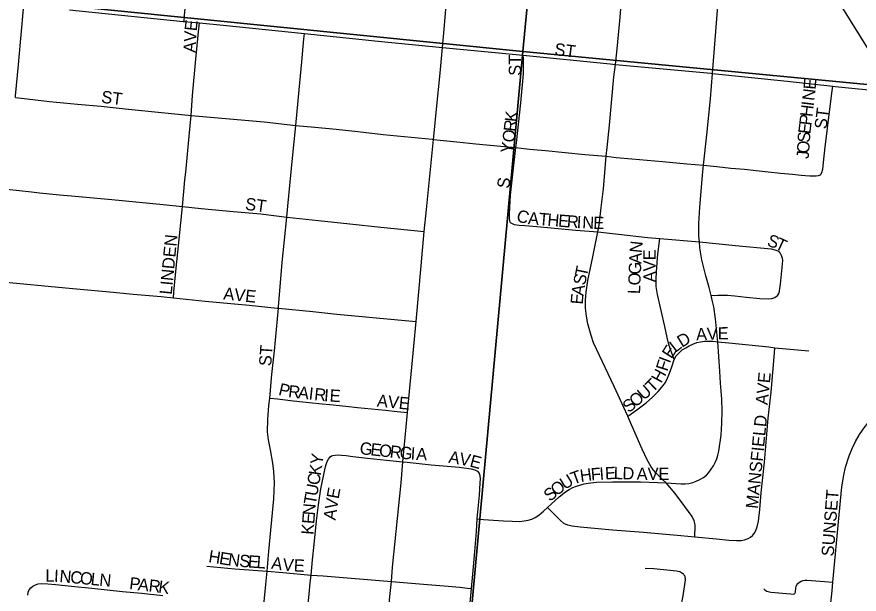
# Model space of a CAD drawing. Extents: x 1410790 to 1770854, y 566777 to 831614.
# Drawn here: x 1601630 to 1605056, y 695774 to 698124 of the extents above; entities that cross this region are included whole.
import ezdxf

# ---------------------------------------------------------------- set-up
doc = ezdxf.new("R2010")
doc.units = 0
for name, color, linetype in [('GM_X_City_Street', 7, 'Continuous'), ('GM_X_City_Street_Text', 7, 'Continuous'), ('GM_X_Section', 7, 'Continuous')]:
    doc.layers.add(name, color=color, linetype=linetype)

msp = doc.modelspace()

# ---------------------------------------------------------------- linework, layer by layer
at = {"layer": 'GM_X_City_Street'}
for points in [[(1602309.9, 698105), (1602312.2, 698129.9), (1602321.5, 698227.3), (1602333.2, 698374.1), (1602342.6, 698477.6)], [(1603360.8, 697999.6), (1603367.6, 698073.2), (1603378.5, 698203.8), (1603388.3, 698316.2), (1603393.6, 698384.7)], [(1604064.4, 697930.5), (1604071.3, 697993.4), (1604082.4, 698107.7), (1604099.4, 698302.8), (1604100.6, 698318.5)], [(1604459.5, 697893.6), (1604481.7, 698166.9), (1604493.3, 698273.6), (1604493.9, 698279.8)], [(1605178.8, 697845.3), (1605169, 697862.3), (1605103.4, 697975.9), (1604982.7, 698169.4), (1604942.5, 698234.5), (1604931.2, 698252.7)], [(1601623.8, 697796.1), (1601624.4, 697802.6), (1601636, 697929.1), (1601638.8, 697959.2), (1601646, 698036.2), (1601658.5, 698171)], [(1601843.6, 698152.1), (1602306.4, 698105.3), (1602309.9, 698105)], [(1602309.9, 698105), (1602372.4, 698099.2)], [(1602339.2, 697722.7), (1602344.4, 697803.4), (1602358.2, 697951.3), (1602368.9, 698063.3), (1602372.4, 698099.2)], [(1602372.4, 698099.2), (1602468.5, 698090.4), (1602799.6, 698056.2)], [(1602764.5, 697681.9), (1602777.5, 697826.8), (1602789, 697940.9), (1602797.6, 698034.8), (1602799.6, 698056.2)], [(1602799.6, 698056.2), (1603099.6, 698025.3), (1603360.8, 697999.6)], [(1603324.8, 697625.2), (1603327.2, 697649.8), (1603337.2, 697747.5), (1603351.1, 697894), (1603360.8, 697999.6)], [(1603360.8, 697999.6), (1603690, 697967.2)], [(1603659.1, 697591.4), (1603661.8, 697610.4), (1603679.5, 697773.9), (1603690.3, 697892.1), (1603690.9, 697923.5), (1603690.3, 697954.1), (1603690, 697967.2)], [(1603690, 697967.2), (1604043.7, 697932.4), (1604064.4, 697930.5)], [(1604026.7, 697556.6), (1604030.7, 697592.2), (1604040.7, 697683.6), (1604058.6, 697879.4), (1604064.4, 697930.5)], [(1604064.4, 697930.5), (1604452.6, 697894.1), (1604459.5, 697893.6)], [(1604422.9, 697519.8), (1604435.9, 697643), (1604451.1, 697790), (1604459.5, 697893.6)], [(1604459.5, 697893.6), (1604763.1, 697862.2), (1604949.2, 697841.1)], [(1604899.4, 697481.4), (1604903.8, 697490.1), (1604908, 697504.2), (1604909.8, 697515.6), (1604911.7, 697530.9), (1604918.5, 697594.7), (1604922.5, 697626.4), (1604930.3, 697693.3), (1604946.9, 697823.2), (1604949.2, 697841.1)], [(1604949.2, 697841.1), (1604958.9, 697840), (1605053.6, 697830.3), (1605096.5, 697827), (1605119.6, 697829.2), (1605136.4, 697831.2), (1605151.9, 697833.9), (1605166.5, 697839), (1605178.8, 697845.3)], [(1601623.8, 697796.1), (1601648.6, 697793.2), (1601762.1, 697779.7), (1601875.8, 697769), (1601973.2, 697760), (1602070.7, 697749.9), (1602232.1, 697732.5), (1602327.1, 697723.8), (1602339.2, 697722.7)], [(1602302.9, 697352.4), (1602308.7, 697413.1), (1602313.5, 697460.3), (1602316.9, 697492.3), (1602331.2, 697638.5), (1602339.2, 697722.7)], [(1602339.2, 697722.7), (1602635.2, 697695.9), (1602764.5, 697681.9)], [(1602727.3, 697308.9), (1602732.5, 697353), (1602750.9, 697549.3), (1602764.5, 697681.9)], [(1602764.5, 697681.9), (1602841.8, 697674.4), (1602928.6, 697666.6), (1603017.2, 697656.9), (1603120, 697645.2), (1603205, 697636.5), (1603319.2, 697625.9), (1603324.8, 697625.2)], [(1603287.2, 697250.7), (1603296.3, 697339.4), (1603324.8, 697625.2)], [(1603324.8, 697625.2), (1603420, 697615.2), (1603496.3, 697607), (1603597.8, 697597.1), (1603659.1, 697591.4)], [(1603636.6, 697287.3), (1603633.3, 697302.9), (1603633.3, 697321.1), (1603634.9, 697348.2), (1603637.5, 697397.9), (1603648.3, 697496.1), (1603659.1, 697591.4)], [(1603659.1, 697591.4), (1603715.5, 697585.8), (1603780, 697579.3), (1603940.4, 697564), (1604026.7, 697556.6)], [(1603992.8, 697248.4), (1603998.2, 697275.9), (1604007.3, 697348.1), (1604016.2, 697424.3), (1604026.7, 697556.6)], [(1604026.7, 697556.6), (1604067, 697551.9), (1604131.5, 697546.3), (1604255.5, 697534.6), (1604355.7, 697525), (1604422.9, 697519.8)], [(1604406.4, 697207.5), (1604404.3, 697232.8), (1604404.1, 697282.4), (1604407.6, 697348.3), (1604419.1, 697479.4), (1604422.9, 697519.8)], [(1604422.9, 697519.8), (1604477.8, 697514.5), (1604534.5, 697508.4), (1604590.3, 697503.2), (1604637.3, 697498.9), (1604686.2, 697492.8), (1604735.9, 697487.5), (1604785.6, 697483.2), (1604819.6, 697479.7), (1604855.3, 697476.3), (1604880.7, 697476.3), (1604890.9, 697477.9), (1604899.4, 697481.4)], [(1601589.2, 697422.4), (1601689.2, 697411.1), (1601721.8, 697407.6), (1601803.3, 697400), (1601852.2, 697396), (1602016.3, 697380.4), (1602224.8, 697360.5), (1602302.9, 697352.4)], [(1602266.3, 696980.4), (1602268.5, 697002.9), (1602275.6, 697073.5), (1602290.2, 697219.3), (1602302.9, 697352.4)], [(1602302.9, 697352.4), (1602379.5, 697344.3), (1602509.9, 697331.8), (1602621.9, 697321.5), (1602727.3, 697308.9)], [(1602694.1, 696938), (1602694.6, 696944), (1602709, 697124.2), (1602727.3, 697308.9)], [(1602727.3, 697308.9), (1602857, 697295), (1602984.4, 697281.7), (1603110.4, 697268.4), (1603287.2, 697250.7)], [(1603636.6, 697287.3), (1603653.1, 697279), (1603672.9, 697275.7), (1603696.1, 697274), (1603744.9, 697269.9), (1603903.3, 697255.4), (1603992.8, 697248.4)], [(1603253.4, 696883.9), (1603274.2, 697110.6), (1603287.2, 697250.7)], [(1604114.9, 696498.4), (1604059, 696619), (1603975.4, 696796.8), (1603965.4, 696826.8), (1603952.1, 696874.2), (1603946.8, 696906), (1603942.7, 696938.2), (1603942.5, 696970.5), (1603945.2, 697002.8), (1603952.3, 697051), (1603972.3, 697147.1), (1603992.8, 697248.4)], [(1603992.8, 697248.4), (1604077, 697239.3), (1604195.5, 697225.8), (1604245.1, 697221.5)], [(1604303.5, 696729.2), (1604298.4, 696743.8), (1604288.6, 696770.1), (1604282.2, 696789.8), (1604275.3, 696819.2), (1604266, 696863.7), (1604235.7, 696993.6), (1604232.7, 697010), (1604231, 697025.9), (1604230, 697043), (1604230.5, 697059.5), (1604231.9, 697085.1), (1604234.4, 697123.5), (1604237, 697157.7), (1604245.1, 697221.5)], [(1604245.1, 697221.5), (1604406.4, 697207.5)], [(1604406.4, 697207.5), (1604552.8, 697192.7), (1604698.3, 697179.1), (1604713.4, 697175.7), (1604720.9, 697173.3), (1604727.5, 697170.2), (1604732.4, 697165.3), (1604736.2, 697160)], [(1604453.8, 696989.1), (1604445.8, 697021.9), (1604432.7, 697070.2), (1604416.5, 697134.2), (1604408.4, 697183.3), (1604406.4, 697207.5)], [(1604724.3, 696990), (1604725.5, 696991), (1604729.1, 696998.1), (1604731.8, 697007.5), (1604734.1, 697018.4), (1604736.4, 697036.3), (1604744.7, 697117.5), (1604745.2, 697133.6), (1604744.5, 697140.8), (1604740.5, 697151.9), (1604736.2, 697160)], [(1601554.3, 697046.8), (1601842.5, 697019.3), (1602021.9, 697002.7), (1602103, 696994.8), (1602216.4, 696985.4), (1602266.3, 696980.4)], [(1602266.3, 696980.4), (1602395.4, 696967.2), (1602574.2, 696949.7), (1602688, 696938.6), (1602694.1, 696938)], [(1604453.8, 696989.1), (1604481.1, 696990.4), (1604500.4, 696991.4), (1604520.6, 696990.4), (1604550.1, 696987.7), (1604597, 696983.1), (1604652.2, 696977.6), (1604686.1, 696976.3), (1604701.4, 696977.6), (1604713.7, 696981.4), (1604724.3, 696990)], [(1604480.7, 696801.4), (1604479.8, 696813.2), (1604471.8, 696894.7), (1604464.5, 696943.2), (1604459.7, 696965.3), (1604453.8, 696989.1)], [(1602658.3, 696572.2), (1602667.2, 696668.3), (1602677.7, 696764.3), (1602694.1, 696938)], [(1602694.1, 696938), (1602834.3, 696924.3), (1602931.9, 696914), (1603209.1, 696888.1), (1603253.4, 696883.9)], [(1603218.5, 696513.9), (1603244.2, 696783.5), (1603253.4, 696883.9)], [(1604270.7, 696227.8), (1604332.1, 696223.4), (1604348.6, 696223.4), (1604363.5, 696224.9), (1604379.9, 696228.6), (1604392.6, 696233.8), (1604407.6, 696240.5), (1604422.5, 696248.8), (1604434.8, 696258.3), (1604445.3, 696269.7), (1604454.7, 696282.5), (1604463.1, 696296.3), (1604470.4, 696310.6), (1604476.8, 696325.4), (1604481.7, 696340.4), (1604484.9, 696356), (1604494.4, 696420.9), (1604498, 696469.6), (1604499, 696518.7), (1604497.2, 696567.7), (1604492.7, 696633), (1604489.9, 696682.2), (1604480.7, 696801.4)], [(1604303.5, 696729.2), (1604312.1, 696743.8), (1604324.9, 696758.3), (1604336.7, 696768), (1604351.2, 696776.4), (1604365.3, 696784.9), (1604380, 696792.1), (1604395.3, 696797.8), (1604411.3, 696801.6), (1604427.5, 696803.5), (1604460.3, 696803.4), (1604480.7, 696801.4)], [(1604480.7, 696801.4), (1604525.6, 696797.1), (1604689.4, 696780.3), (1604713.6, 696777.1)], [(1604623.6, 696014.8), (1604629, 696021.4), (1604636, 696033), (1604641.8, 696048.1), (1604646.1, 696071.2), (1604651.7, 696119.3), (1604657.3, 696186.8), (1604671.4, 696311.2), (1604686.1, 696490.7), (1604698.2, 696596.9), (1604711.7, 696756.6), (1604713.6, 696777.1)], [(1604713.6, 696777.1), (1604851.8, 696764.6)], [(1604114.9, 696498.4), (1604151.8, 696524.9), (1604189.8, 696553.4), (1604215.5, 696575.5), (1604238.5, 696599.6), (1604254, 696616.6), (1604267.7, 696636.2), (1604277.1, 696653.3), (1604284.8, 696673), (1604294.2, 696699.4), (1604303.5, 696729.2)], [(1605056.2, 696421.1), (1605057.8, 696423.8), (1605076, 696450.6), (1605106.2, 696488.8), (1605139.3, 696524.4), (1605163.1, 696546.3), (1605188.3, 696566.5), (1605215, 696584.7), (1605242.9, 696601), (1605272, 696615.2), (1605301.9, 696627.7), (1605332.5, 696638.4), (1605363.7, 696647.2), (1605395.3, 696654.1), (1605427.3, 696659), (1605459.6, 696661.9), (1605491.9, 696662.6), (1605524.2, 696661.1), (1605556.3, 696657.3), (1605588.2, 696651.4), (1605619.6, 696643.5), (1605665.9, 696628.6), (1605726.9, 696605.4), (1605728.5, 696604.7)], [(1602647.3, 695867.3), (1602654.8, 695949.2), (1602674.9, 696161.7), (1602678, 696226.7), (1602675.6, 696272.8), (1602670.7, 696307.2), (1602661.6, 696361.9), (1602653.2, 696401.8), (1602649.7, 696435.5), (1602651.1, 696484.6), (1602654.6, 696541.4), (1602658.3, 696572.2)], [(1602658.3, 696572.2), (1602689.6, 696568.7), (1602711.3, 696566.3), (1602743.4, 696562.8), (1602780.8, 696558.9), (1602818.9, 696554.8), (1602871.6, 696549.1), (1602902.4, 696545.9), (1602967.8, 696538.8), (1603016, 696533.9), (1603128.9, 696523.1), (1603177.2, 696518.1), (1603218.5, 696513.9)], [(1603200.3, 696313.3), (1603211.5, 696440.3), (1603218.5, 696513.9)], [(1604270.7, 696227.8), (1604257.5, 696239.8), (1604229.4, 696267.5), (1604219, 696279.4), (1604209.9, 696292.4), (1604194.3, 696320.5), (1604173.6, 696364.9), (1604121.1, 696485), (1604114.9, 696498.4)], [(1604949, 695822.9), (1604974.2, 696097.2), (1604985.6, 696210.8), (1604993.5, 696258.9), (1605000.9, 696290.4), (1605015.4, 696336.8), (1605027.4, 696366.8), (1605041.5, 696395.9), (1605056.2, 696421.1)], [(1602826.3, 695852.1), (1602831.9, 695914.1), (1602838.8, 695976), (1602848.8, 696072), (1602856.1, 696137.2), (1602866, 696202.2), (1602882.4, 696280), (1602886.3, 696298.3), (1602891.3, 696313.6), (1602897, 696323.8), (1602901.5, 696329.3), (1602904.7, 696332.6)], [(1602904.7, 696332.6), (1602909.9, 696336.5), (1602914.9, 696338.5), (1602924.5, 696340), (1602939.3, 696341.3), (1602950.7, 696340), (1602969.6, 696338.7), (1602996.2, 696334.9), (1603056.5, 696328.1), (1603133.9, 696319.8), (1603200.3, 696313.3)], [(1603153.3, 695825.6), (1603157.9, 695884.6), (1603192.7, 696227.6), (1603200.3, 696313.3)], [(1603200.3, 696313.3), (1603218, 696311.2), (1603315.4, 696300.1), (1603429.3, 696290.8), (1603477.7, 696284.4), (1603493.3, 696280.2), (1603506.3, 696273.4)], [(1603502.4, 696080.1), (1603503.4, 696095.5), (1603511.4, 696177.5), (1603513.1, 696201), (1603514.9, 696226.8), (1603515.5, 696243), (1603514.4, 696256.4), (1603511.9, 696264.7), (1603506.3, 696273.4)], [(1603788, 696127), (1603802.7, 696140.5), (1603836.3, 696170.7), (1603862.1, 696190.9), (1603876, 696200.1), (1603890.9, 696208), (1603906.4, 696214.2), (1603938.1, 696223.4), (1603954.4, 696226.5), (1603987.2, 696229.4), (1604052.4, 696231.9), (1604166.1, 696230.7), (1604270.7, 696227.8)], [(1604387.4, 696007.5), (1604388.1, 696019.5), (1604389.5, 696040.3), (1604389.6, 696056.8), (1604385.1, 696073.2), (1604376.4, 696090.2), (1604347.2, 696130.5), (1604308, 696183.8), (1604270.7, 696227.8)], [(1603502.4, 696080.1), (1603527.3, 696078.4), (1603609.6, 696073), (1603644.8, 696070.8), (1603673, 696070.4), (1603693.9, 696072.2), (1603709, 696074.8), (1603724.7, 696078.9), (1603738.1, 696085.8), (1603753.3, 696096), (1603772.2, 696112.3), (1603788, 696127)], [(1603788, 696127), (1603799.2, 696115.8), (1603829.2, 696086.1), (1603840.8, 696073.9), (1603853.3, 696063.4), (1603869.6, 696056.8), (1603888.2, 696052.1), (1603921.5, 696048.1), (1604052.5, 696036.3), (1604178.3, 696026.2), (1604330.6, 696012.7), (1604387.4, 696007.5)], [(1603479.2, 695797.4), (1603484.6, 695855), (1603490.8, 695931.3), (1603499.2, 696029.7), (1603502.4, 696080.1)], [(1604387.4, 696007.5), (1604476.3, 695999.3), (1604526.1, 695993.6), (1604557.3, 695992.1), (1604575.6, 695993.2), (1604589.8, 695995.9), (1604604.3, 696000.8), (1604614.5, 696006.3), (1604622.6, 696013.6), (1604623.6, 696014.8)], [(1602401.8, 695888.6), (1602516, 695877.9), (1602647.3, 695867.3)], [(1604329.9, 695715.7), (1604330.5, 695718.8), (1604340.2, 695767.2), (1604349.1, 695832.6), (1604349.3, 695837.1), (1604348.8, 695841.2), (1604347.8, 695845.4), (1604346.5, 695848.7), (1604343.6, 695853.1), (1604341, 695856.1), (1604335.3, 695860.1), (1604331.4, 695862.3), (1604326.5, 695864.4), (1604313.3, 695867.1), (1604221.3, 695876.6), (1604185, 695879)], [(1602600.2, 695383.3), (1602605.1, 695430.5), (1602607.6, 695457.4), (1602612.5, 695498.7), (1602620, 695574.7), (1602639.8, 695785.9), (1602647.3, 695867.3)], [(1602647.3, 695867.3), (1602712.2, 695862.1), (1602826.3, 695852.1)], [(1602780.2, 695361.6), (1602782, 695380.1), (1602785.8, 695420.3), (1602789.4, 695469.2), (1602802.8, 695617.7), (1602818.6, 695774.4), (1602823.1, 695820.4), (1602826.3, 695852.1)], [(1602826.3, 695852.1), (1602875.6, 695848.1), (1603153.3, 695825.6)], [(1601673.9, 695770.5), (1601676.2, 695782), (1601679.8, 695792.2), (1601686.3, 695800.1), (1601695, 695806.6), (1601705.1, 695812.5), (1601716, 695816.1), (1601731.2, 695817.5), (1601755.1, 695816.8), (1601786.2, 695813.9), (1601852.1, 695806.6), (1601934.7, 695798.7), (1602060, 695784.6), (1602136.7, 695777.7), (1602222.8, 695768.9)], [(1603105.7, 695332), (1603107.5, 695351.3), (1603116.9, 695450.6), (1603127.6, 695558.3), (1603146.8, 695764.1), (1603153.3, 695825.6)], [(1603153.3, 695825.6), (1603284.5, 695814.6), (1603383.7, 695806.4), (1603431.8, 695802.2), (1603462.4, 695798.6), (1603479.2, 695797.4)], [(1604668, 695796), (1604674.2, 695790.2), (1604680.6, 695786), (1604696.4, 695782.2), (1604776.9, 695775), (1604789.3, 695774.5), (1604792.6, 695775.7), (1604794.7, 695777.3), (1604796.3, 695779.5), (1604797.2, 695781.8), (1604799.2, 695799.3), (1604800.4, 695805.9), (1604803.2, 695811.5), (1604807.3, 695817.4), (1604813.5, 695823.3), (1604820.6, 695827.3), (1604828.3, 695829.6), (1604835.7, 695830.6), (1604844.6, 695830.8), (1604914.8, 695825.5), (1604949, 695822.9)], [(1604917.8, 695488.6), (1604921.6, 695543.7), (1604930.7, 695641.5), (1604945.8, 695787.8), (1604949, 695822.9)], [(1603444.5, 695332.5), (1603446.4, 695406.4), (1603448.1, 695454.4), (1603452.7, 695520), (1603479.2, 695797.4)]]:
    msp.add_lwpolyline(points, dxfattribs=at)
at = {"layer": 'GM_X_Section'}
for points in [[(1598860.7, 703731.2), (1604192.4, 703233.9), (1603688.3, 697982.3), (1598351.3, 698519.7)], [(1604192.4, 703233.9), (1609553.2, 702682.3), (1609051.7, 697468.6), (1603688.3, 697982.3)], [(1598351.3, 698519.7), (1603688.3, 697982.3), (1603189.9, 692572.7), (1597838.4, 693072.3)], [(1609051.7, 697468.6), (1608507.1, 692045.6), (1603189.9, 692572.7), (1603688.3, 697982.3)]]:
    msp.add_lwpolyline(points, close=True, dxfattribs=at)

# ---------------------------------------------------------------- texts
at = {"layer": 'GM_X_City_Street_Text'}
for s, rotation, p in [('E', 83.7307, (1602361.1, 698063.9)), ('V', 86.8074, (1602358.8, 698020.7)), ('A', 86.8511, (1602356.3, 697976.8)), ('ST', 352.8783, (1603814.5, 697968.1)), ('ST', 90, (1603680.7, 697884)), ('E', 85.3737, (1604879, 697826.3)), ('ST', 352.8716, (1601970.9, 697774.5)), ('N', 83.1203, (1604873.5, 697780.5)), ('H', 83.1203, (1604865.6, 697715)), ('I', 83.1216, (1604870.9, 697758.7)), ('K', 83.5391, (1603663.4, 697694)), ('ST', 82.8649, (1604923.4, 697664.9)), ('R', 83.5541, (1603659, 697654.7)), ('P', 83.1257, (1604861.4, 697680)), ('O', 82.9716, (1603653.5, 697610.5)), ('E', 83.6764, (1604857.6, 697645.2)), ('S', 86.3119, (1604855.3, 697610.6)), ('Y', 80.27, (1603645.7, 697564.6)), ('O', 86.3037, (1604852.5, 697566.7)), ('J', 86.3255, (1604851.1, 697544.8)), ('S', 82.88, (1603632.4, 697423.1)), ('ST', 352.4092, (1602556.2, 697338.9)), ('C', 343.9078, (1603658.5, 697293.3)), ('A', 355.6573, (1603707.5, 697280.3)), ('T', 355.1456, (1603751.3, 697277)), ('H', 355.1561, (1603786.4, 697274)), ('E', 355.1649, (1603830.2, 697270.3)), ('R', 355.5982, (1603865.7, 697267.3)), ('I', 356.7775, (1603906.3, 697264.2)), ('N', 357.3807, (1603928.8, 697262.9)), ('E', 358.4612, (1603973.8, 697260.8)), ('LINDEN', 84.5107, (1602259.6, 696991.7)), ('S', 340.8092, (1604678, 697193.5)), ('T', 335.1943, (1604710.1, 697182.4)), ('N', 84.0219, (1604171.5, 697161.1)), ('A', 87.6609, (1604169.7, 697117.9)), ('AVE', 90, (1604228.7, 697043.6)), ('T', 78.2239, (1603948.1, 697063.4)), ('G', 87.6566, (1604167.9, 697074)), ('O', 87.6605, (1604166.1, 697030)), ('S', 78.3927, (1603941, 697028.9)), ('AVE', 354.0932, (1602467.9, 696973.7)), ('A', 81.312, (1603934.5, 696986.1)), ('L', 87.6772, (1604164.7, 696994.9)), ('E', 85.0492, (1603931.5, 696951.9)), ('A', 2.81, (1604393.6, 696806.6)), ('V', 2.4487, (1604437.5, 696808.7)), ('E', 0.6011, (1604481, 696810.6)), ('D', 31.2224, (1604335.1, 696776.3)), ('ST', 86.1879, (1602664.3, 696701)), ('E', 57.2648, (1604292.5, 696729.4)), ('L', 37.6077, (1604308.5, 696755.7)), ('I', 69.4567, (1604286, 696711.3)), ('F', 72.5479, (1604275.7, 696678.4)), ('H', 61.7329, (1604250.9, 696630.1)), ('AVE', 84.2973, (1604683.9, 696542.5)), ('P', 346.1758, (1602690.9, 696585.8)), ('T', 44.87, (1604216.4, 696592.5)), ('R', 353.0991, (1602731.6, 696576.2)), ('A', 353.7004, (1602771.4, 696571.4)), ('I', 353.6936, (1602815.2, 696566.5)), ('R', 354.2425, (1602837.6, 696564.1)), ('I', 355.6525, (1602878.3, 696560)), ('E', 356.1331, (1602900.7, 696558.3)), ('U', 40.5323, (1604179.9, 696561.1)), ('AVE', 354.0953, (1603092.7, 696538.1)), ('S', 40.5331, (1604119.7, 696509.6)), ('O', 40.5219, (1604146.4, 696532.5)), ('MANSFIELD', 84.289, (1604644.3, 696120.3)), ('G', 353.6827, (1603022.4, 696344.5)), ('E', 353.6749, (1603066.1, 696339.7)), ('O', 353.6779, (1603101.1, 696335.8)), ('R', 353.6867, (1603144.8, 696330.9)), ('G', 354.5189, (1603185, 696326.5)), ('I', 356.3504, (1603230.5, 696322.2)), ('A', 356.767, (1603252.9, 696320.7)), ('Y', 81.3784, (1602872.2, 696298.3)), ('A', 350.1712, (1603383.4, 696309.3)), ('V', 350.1712, (1603426.8, 696301.8)), ('E', 344.8371, (1603468.9, 696294.5)), ('K', 81.3977, (1602865.6, 696254.8)), ('F', 4.6093, (1603966.5, 696236.7)), ('I', 4.2663, (1604001.5, 696239.5)), ('E', 2.3097, (1604023, 696241.2)), ('L', 358.7297, (1604057.3, 696242.6)), ('D', 357.8579, (1604092.3, 696241.8)), ('C', 81.1093, (1602859.4, 696215.4)), ('U', 31.5166, (1603858.1, 696197.6)), ('T', 20.0765, (1603893.3, 696219.5)), ('H', 7.6943, (1603923.6, 696230.9)), ('A', 359.182, (1604150.7, 696239.6)), ('V', 359.9703, (1604195.5, 696239)), ('E', 359.9956, (1604239.5, 696239)), ('U', 79.5603, (1602851.2, 696170.7)), ('O', 38.868, (1603825.3, 696171)), ('E', 80.0055, (1602938.5, 696159.8)), ('S', 39.6691, (1603798.3, 696148.7)), ('SUNSET', 85.6037, (1604952.3, 695926.7)), ('T', 80.1986, (1602845.3, 696136.2)), ('V', 81.3784, (1602932, 696116.6)), ('N', 85.5585, (1602842, 696093.5)), ('E', 85.5699, (1602839.3, 696058.4)), ('A', 81.5546, (1602925.5, 696073.1)), ('K', 85.5803, (1602835.9, 696014.6)), ('H', 350.9796, (1602406.8, 695904.4)), ('E', 350.9667, (1602450.3, 695897.5)), ('N', 352.6608, (1602486.6, 695891.8)), ('S', 355.6711, (1602533.1, 695885.9)), ('E', 355.9066, (1602568.4, 695883.2)), ('L', 355.9118, (1602603.6, 695880.7)), ('A', 351.1915, (1602662.2, 695878)), ('V', 355.2857, (1602709.6, 695870.8)), ('E', 356.7915, (1602754.9, 695867.1)), ('L', 359.0301, (1601745.1, 695825.4)), ('I', 357.1354, (1601779.9, 695824.8)), ('N', 354.7917, (1601801.3, 695823.7)), ('C', 354.6132, (1601845.1, 695819.7)), ('O', 354.6088, (1601884.5, 695816)), ('L', 354.6102, (1601928.3, 695811.9)), ('N', 354.6047, (1601963.3, 695808.6)), ('P', 353.3596, (1602085.2, 695794.5)), ('A', 353.362, (1602120.1, 695790.4)), ('R', 353.3694, (1602163.8, 695785.4)), ('K', 351.8421, (1602202.8, 695780.8))]:
    msp.add_text(s, height=50, rotation=rotation, dxfattribs=at).set_placement(p)

doc.saveas('drawing.dxf')
